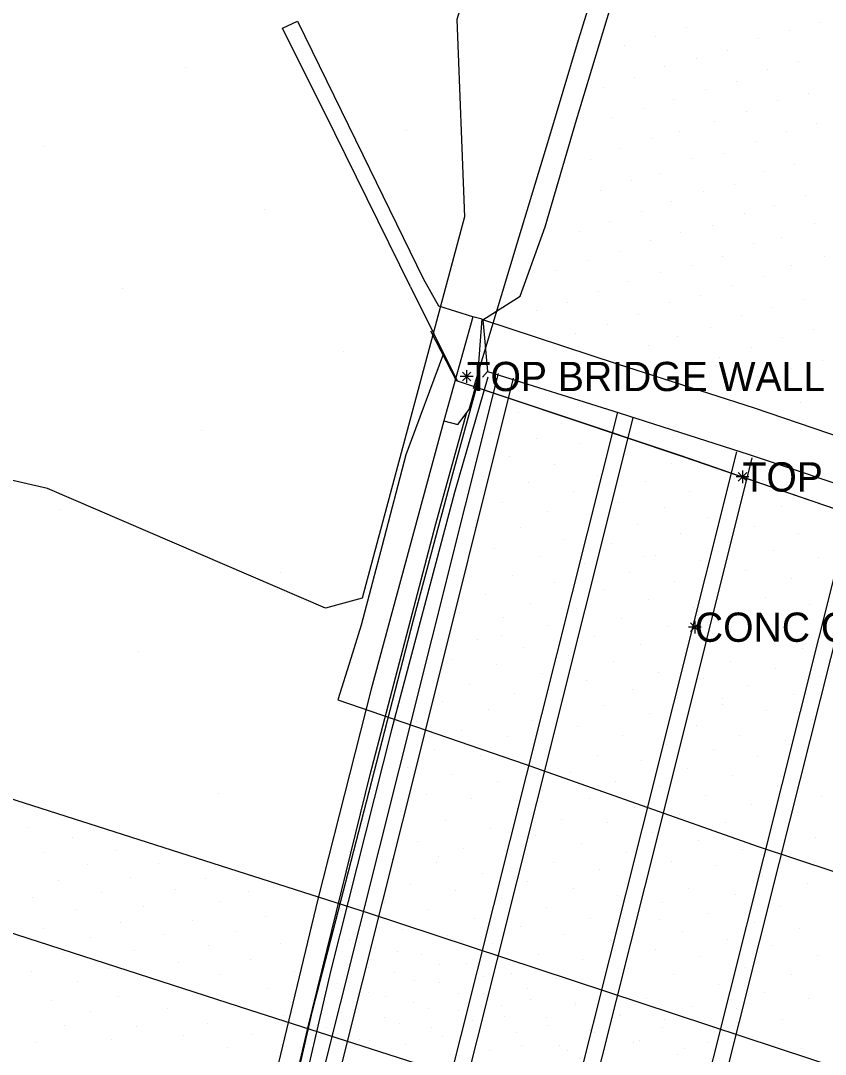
# Model space of a CAD drawing. Extents: x 1733582 to 1734070, y 467256 to 468256.
# Drawn here: x 1733826.4 to 1733875.9, y 467813.1 to 467876.7 of the extents above; entities that cross this region are included whole.
import ezdxf

# ---------------------------------------------------------------- set-up
doc = ezdxf.new("R2010")
doc.units = 0
for name, color, linetype in [('Default', 7, 'Continuous'), ('S_Bridge_Abutment_Bottom', 7, 'Continuous'), ('S_Bridge_Curb', 7, 'Continuous'), ('S_Bridge_Deck', 7, 'Continuous'), ('S_Bridge_ExpansionJoint', 7, 'Continuous'), ('S_Bridge_Parapet', 7, 'Continuous'), ('S_Bridge_Rail', 7, 'Continuous'), ('S_Bridge_Wingwall', 7, 'Continuous'), ('S_Ground_LevelString', 7, 'Continuous'), ('S_Ground_SpotElevation', 7, 'Continuous'), ('S_Guardrail_Beam', 7, 'Continuous'), ('S_Misc_MiscFeature', 7, 'Continuous'), ('S_Misc_MiscItems', 7, 'Continuous'), ('S_Roadway_Edge_Pavement', 7, 'Continuous'), ('S_Roadway_Painted_Lines', 7, 'Continuous'), ('S_Text', 7, 'Continuous'), ('S_Trees_Bush_Line', 7, 'Continuous')]:
    doc.layers.add(name, color=color, linetype=linetype)

# ---------------------------------------------------------------- blocks, each defined once
blk = doc.blocks.new('POINT_DISPLAY')
at = {"layer": 'Default'}
blk.add_line((0, 0), (0, 0), dxfattribs=at)

msp = doc.modelspace()

# ---------------------------------------------------------------- linework, layer by layer
at = {"layer": 'S_Bridge_Abutment_Bottom'}
for points in [[(1733850.373, 467860.35), (1733853.263, 467854.563), (1733867.149, 467849.901), (1733879.209, 467845.764), (1733887.663, 467842.899), (1733893.569, 467845.839)], [(1733852.42, 467856.251), (1733850.086, 467849.997), (1733848.643, 467844.425), (1733847.351, 467839.52), (1733846.701, 467837.477), (1733845.911, 467834.929), (1733857.447, 467830.97), (1733871.792, 467825.895), (1733883.518, 467822.024), (1733885.278, 467828.551), (1733887.725, 467837.781), (1733888.645, 467841.491), (1733889.276, 467843.701)]]:
    msp.add_lwpolyline(points, dxfattribs=at)
at = {"layer": 'S_Bridge_Curb'}
msp.add_lwpolyline([(1733818.159, 467663.732), (1733819.385, 467674.582), (1733820.64, 467684.116), (1733822.243, 467697.564), (1733823.972, 467709.579), (1733825.87, 467722.342), (1733827.859, 467734.138), (1733830.216, 467748.192), (1733832.11, 467758.256), (1733834.51, 467770.45), (1733837.898, 467787.063), (1733840.865, 467800.549), (1733844.359, 467815.787), (1733847.831, 467829.289), (1733850.56, 467839.861), (1733853.05, 467849.061), (1733854.563, 467854.584)], dxfattribs=at)
at = {"layer": 'S_Bridge_Deck'}
msp.add_line((1733854.822, 467854.785), (1733855.12, 467855.138), dxfattribs=at)
msp.add_lwpolyline([(1733855.138, 467854.785), (1733853.086, 467847.693), (1733849.22, 467833.073), (1733845.482, 467818.291), (1733842.048, 467803.532), (1733838.704, 467788.663), (1733835.558, 467773.547), (1733832.728, 467759.072), (1733829.896, 467743.681), (1733827.379, 467728.743), (1733824.957, 467713.563), (1733822.869, 467698.529), (1733821.029, 467683.583), (1733819.201, 467668.729), (1733818.621, 467663.409)], dxfattribs=at)
at = {"layer": 'S_Bridge_ExpansionJoint'}
for points in [[(1733888.515, 467847.187), (1733886.678, 467847.805), (1733878.85, 467850.396), (1733871.551, 467852.887), (1733863.133, 467855.581), (1733854.845, 467858.314)], [(1733888.515, 467847.187), (1733886.678, 467847.805), (1733878.85, 467850.396), (1733871.551, 467852.887), (1733863.133, 467855.581), (1733854.845, 467858.314), (1733855.12, 467855.138), (1733863.226, 467852.582), (1733871.238, 467850.017), (1733878.782, 467847.499), (1733886.695, 467844.816), (1733888.515, 467847.187)]]:
    msp.add_lwpolyline(points, dxfattribs=at)
at = {"layer": 'S_Bridge_Parapet'}
msp.add_lwpolyline([(1733853.286, 467851.862), (1733854, 467852.799), (1733854.498, 467854.603), (1733854.801, 467858.354), (1733854.221, 467858.497), (1733852.432, 467852.088), (1733853.286, 467851.862)], dxfattribs=at)
at = {"layer": 'S_Bridge_Rail'}
msp.add_lwpolyline([(1733818.359, 467665.855), (1733819.171, 467673.048), (1733821.039, 467688.917), (1733823.113, 467704.785), (1733825.46, 467720.602), (1733828.058, 467736.434), (1733830.845, 467752.168), (1733833.805, 467767.85), (1733837.016, 467783.594), (1733840.405, 467799.172), (1733844.065, 467814.724), (1733847.908, 467830.326), (1733851.933, 467845.769), (1733853.853, 467852.641)], dxfattribs=at)
at = {"layer": 'S_Bridge_Wingwall'}
for points in [[(1733850.373, 467860.35), (1733845.718, 467869.802), (1733842.498, 467876.263), (1733843.416, 467876.693)], [(1733850.373, 467860.35), (1733845.718, 467869.802), (1733842.498, 467876.263), (1733843.416, 467876.693)], [(1733843.416, 467876.693), (1733847.44, 467868.46), (1733851.164, 467860.849)], [(1733851.164, 467860.849), (1733852.099, 467859.174), (1733854.191, 467858.512)]]:
    msp.add_lwpolyline(points, dxfattribs=at)
at = {"layer": 'S_Ground_LevelString'}
msp.add_lwpolyline([(1733852.42, 467856.251), (1733850.086, 467849.997), (1733848.643, 467844.425), (1733847.351, 467839.52), (1733846.701, 467837.477), (1733845.911, 467834.929), (1733857.447, 467830.97), (1733871.792, 467825.895), (1733883.518, 467822.024), (1733885.278, 467828.551), (1733887.725, 467837.781), (1733888.645, 467841.491), (1733889.276, 467843.701)], dxfattribs=at)
at = {"layer": 'S_Guardrail_Beam'}
msp.add_lwpolyline([(1733854.27, 467854.097), (1733857.079, 467863.421), (1733858.901, 467869.438), (1733860.667, 467875.345), (1733863.417, 467884.252), (1733867.149, 467896.174), (1733870.976, 467908.127), (1733874.829, 467920.063), (1733878.684, 467931.805), (1733882.613, 467943.748), (1733886.481, 467955.744), (1733888.25, 467961.715), (1733889.83, 467967.648), (1733891.464, 467973.858), (1733891.813, 467975.524), (1733892.138, 467977.915), (1733892.283, 467980.088), (1733892.308, 467981.408), (1733892.214, 467983.277), (1733891.951, 467985.659), (1733891.686, 467987.183)], dxfattribs=at)
at = {"layer": 'S_Misc_MiscFeature'}
for points in [[(1733851.612, 467857.638), (1733853.196, 467854.581), (1733859.544, 467852.463), (1733859.587, 467852.455), (1733866.898, 467850.008), (1733866.968, 467849.988), (1733874.19, 467847.475), (1733874.253, 467847.466), (1733881.575, 467844.967), (1733881.654, 467844.95), (1733887.649, 467842.907), (1733890.85, 467844.587)], [(1733851.612, 467857.638), (1733853.196, 467854.581), (1733859.544, 467852.463), (1733859.587, 467852.455), (1733866.898, 467850.008), (1733866.968, 467849.988), (1733874.19, 467847.475), (1733874.253, 467847.466), (1733881.575, 467844.967), (1733881.654, 467844.95), (1733887.649, 467842.907), (1733890.85, 467844.587)], [(1733819.146, 467662.128), (1733822.411, 467687.138), (1733825.625, 467712.064), (1733828.308, 467732.621), (1733831.184, 467747.947), (1733833.505, 467760.094), (1733835.806, 467771.99), (1733838.257, 467784.633), (1733839.477, 467789.916), (1733843.642, 467806.605), (1733849.69, 467830.62), (1733855.796, 467855.018)], [(1733820.122, 467661.91), (1733823.472, 467687.541), (1733826.672, 467712.367), (1733829.355, 467732.542), (1733832.44, 467748.988), (1733834.659, 467760.701), (1733836.916, 467772.404), (1733839.778, 467786.991), (1733844.946, 467807.685), (1733851.172, 467832.455), (1733856.733, 467854.727)], [(1733826.53, 467660.119), (1733830.278, 467688.775), (1733833.202, 467711.396), (1733835.635, 467730.109), (1733838.854, 467747.125), (1733841.053, 467758.65), (1733843.35, 467770.62), (1733845.821, 467783.336), (1733847.212, 467789.204), (1733851.47, 467806.186), (1733857.516, 467830.268), (1733863.15, 467852.64)], [(1733852.432, 467852.088), (1733847.956, 467835.582), (1733844.668, 467822.664), (1733840.962, 467807.205), (1733837.376, 467791.545), (1733834.11, 467775.918), (1733831.093, 467760.248), (1733828.17, 467744.438), (1733825.424, 467728.718), (1733822.802, 467711.353), (1733820.741, 467696.705), (1733817.897, 467673.275), (1733817.169, 467667.027)], [(1733864.079, 467852.275), (1733858.131, 467828.607), (1733852.049, 467804.339), (1733847.192, 467785.066), (1733844.207, 467769.696), (1733841.988, 467758.102), (1733839.394, 467744.549), (1733836.696, 467730.312), (1733833.835, 467708.583), (1733831.31, 467688.992), (1733827.509, 467659.844)], [(1733833.862, 467657.682), (1733837.178, 467683.156), (1733840.254, 467706.86), (1733843.003, 467727.895), (1733846.149, 467744.535), (1733848.346, 467756.071), (1733850.647, 467768.07), (1733853.573, 467783.047), (1733858.608, 467802.95), (1733864.671, 467827.038), (1733870.472, 467850.181)], [(1733871.393, 467849.822), (1733865.695, 467826.963), (1733859.504, 467802.42), (1733854.508, 467782.647), (1733851.621, 467767.768), (1733849.286, 467755.703), (1733847.085, 467744.185), (1733843.99, 467727.733), (1733841.143, 467705.862), (1733838.187, 467683.149), (1733834.828, 467657.424)], [(1733841.162, 467655.238), (1733844.601, 467681.503), (1733847.732, 467705.748), (1733850.338, 467725.565), (1733853.469, 467742.079), (1733855.705, 467753.836), (1733857.987, 467765.604), (1733860.885, 467780.409), (1733865.914, 467800.487), (1733872.136, 467825.216), (1733877.778, 467847.684)], [(1733878.753, 467847.484), (1733873.086, 467824.941), (1733866.9, 467800.334), (1733861.829, 467780.055), (1733858.912, 467765.093), (1733856.608, 467753.207), (1733854.359, 467741.368), (1733851.322, 467725.26), (1733848.676, 467705.17), (1733845.544, 467680.934), (1733842.168, 467654.979)]]:
    msp.add_lwpolyline(points, dxfattribs=at)
at = {"layer": 'S_Misc_MiscItems'}
for p, q in [((1733854.1, 467854.566), (1733853.576, 467855.09)), ((1733854.1, 467855.09), (1733853.576, 467854.566)), ((1733853.838, 467855.221), (1733853.838, 467854.435)), ((1733854.231, 467854.828), (1733853.445, 467854.828)), ((1733871.216, 467848.646), (1733870.43, 467848.646)), ((1733871.085, 467848.384), (1733870.561, 467848.908)), ((1733871.085, 467848.908), (1733870.561, 467848.384)), ((1733870.823, 467849.039), (1733870.823, 467848.253)), ((1733868.153, 467839.136), (1733867.629, 467839.66)), ((1733868.153, 467839.66), (1733867.629, 467839.136)), ((1733867.891, 467839.791), (1733867.891, 467839.005)), ((1733868.284, 467839.398), (1733867.498, 467839.398))]:
    msp.add_line(p, q, dxfattribs=at)
at = {"layer": 'S_Roadway_Edge_Pavement'}
for points in [[(1733854.845, 467858.314), (1733857.128, 467859.768), (1733858.674, 467864.047), (1733860.603, 467870.622), (1733863.432, 467879.992), (1733866.984, 467890.771), (1733869.633, 467899.006), (1733872.574, 467908.264), (1733875.889, 467918.696)], [(1734069.119, 467746.597), (1734001.211, 467770.208), (1733956.123, 467785.373), (1733927.716, 467795.111), (1733887.65, 467808.651), (1733847.805, 467821.807), (1733798.866, 467837.428), (1733790.266, 467840.778), (1733759.652, 467856.03), (1733727.307, 467874.285), (1733717.915, 467873.615), (1733694.164, 467877.415), (1733655.646, 467887.316), (1733629.579, 467895.037)]]:
    msp.add_lwpolyline(points, dxfattribs=at)
at = {"layer": 'S_Roadway_Painted_Lines'}
msp.add_lwpolyline([(1733625.204, 467882.39), (1733667.524, 467869.887), (1733714.43, 467855.622), (1733753.6, 467843.716), (1733799.459, 467829.092), (1733840.473, 467815.848), (1733894.111, 467798.664), (1733961.084, 467775.678), (1734014.318, 467757.225), (1734066.93, 467738.782)], dxfattribs=at)
at = {"layer": 'S_Trees_Bush_Line'}
msp.add_lwpolyline([(1733864.99, 467914.699), (1733853.241, 467876.8), (1733853.702, 467864.648), (1733847.41, 467841.194), (1733845.154, 467840.576), (1733828.035, 467847.94), (1733810.332, 467852), (1733780.088, 467867.503), (1733752.541, 467872.718), (1733724.887, 467879.082), (1733700.627, 467880.361), (1733664.82, 467890.7), (1733633.561, 467903.194)], dxfattribs=at)

# ---------------------------------------------------------------- block references
at = {"layer": 'S_Ground_SpotElevation'}
for p in [(1733875.587, 467876.608), (1733867.371, 467876.303), (1733873.706, 467876.117), (1733865.476, 467875.748), (1733871.809, 467875.616), (1733863.542, 467875.214), (1733869.893, 467874.902), (1733867.978, 467874.383), (1733874.263, 467874.198), (1733836.545, 467873.821), (1733866.037, 467873.883), (1733872.388, 467873.738), (1733864.152, 467873.242), (1733870.464, 467873.007), (1733862.247, 467872.606), (1733868.57, 467872.503), (1733874.856, 467872.249), (1733866.586, 467871.843), (1733872.962, 467871.841), (1733864.714, 467871.335), (1733871.044, 467871.128), (1733862.837, 467870.759), (1733869.127, 467870.492), (1733875.407, 467870.41), (1733850.147, 467869.949), (1733866.954, 467869.902), (1733873.555, 467869.89), (1733827.808, 467868.956), (1733865.3, 467869.468), (1733871.634, 467869.264), (1733863.319, 467868.831), (1733869.723, 467868.562), (1733861.439, 467868.168), (1733867.745, 467868.213), (1733874.05, 467867.872), (1733865.802, 467867.307), (1733872.205, 467867.42), (1733863.984, 467866.911), (1733870.305, 467866.627), (1733862.06, 467866.27), (1733868.424, 467866.195), (1733874.698, 467865.993), (1733841.41, 467865.084), (1733866.433, 467865.61), (1733872.774, 467865.339), (1733864.591, 467865.008), (1733870.915, 467864.877), (1733862.603, 467864.347), (1733868.954, 467864.1), (1733875.251, 467864.22), (1733860.783, 467863.779), (1733865.127, 467863.18), (1733867.001, 467863.698), (1733873.208, 467863.375), (1733871.491, 467862.999), (1733861.262, 467861.975), (1733863.237, 467862.495), (1733869.565, 467862.214), (1733875.879, 467862.217), (1733859.308, 467861.374), (1733867.675, 467861.684), (1733873.836, 467861.627), (1733863.772, 467860.694), (1733865.76, 467861.206), (1733872.083, 467860.953), (1733832.674, 467860.219), (1733861.95, 467860.027), (1733870.127, 467860.449), (1733860.043, 467859.394), (1733866.332, 467859.35), (1733868.229, 467859.829), (1733874.569, 467859.589), (1733858.114, 467858.886), (1733872.685, 467859.085), (1733864.4, 467858.619), (1733870.757, 467858.562), (1733860.564, 467857.484), (1733862.502, 467858.056), (1733868.856, 467857.861), (1733875.184, 467857.742), (1733866.821, 467857.287), (1733873.254, 467857.212), (1733846.275, 467856.347), (1733865.006, 467856.711), (1733871.369, 467856.622), (1733869.424, 467855.975), (1733875.741, 467855.826), (1733867.532, 467855.475), (1733873.848, 467855.304), (1733871.749, 467854.826), (1733874.373, 467853.252), (1733857.019, 467852.591), (1733859.659, 467851.91), (1733837.539, 467851.482), (1733855.323, 467851.346), (1733862.458, 467851.65), (1733858.13, 467851.01), (1733860.804, 467850.682), (1733865.083, 467850.901), (1733856.503, 467849.904), (1733863.615, 467850.024), (1733859.233, 467849.437), (1733866.431, 467849.443), (1733854.866, 467848.691), (1733861.923, 467848.733), (1733869.309, 467849.024), (1733857.656, 467848.283), (1733864.838, 467848.342), (1733872.032, 467848.448), (1733860.446, 467847.746), (1733867.576, 467847.739), (1733870.439, 467847.394), (1733874.643, 467847.762), (1733828.802, 467846.617), (1733856.02, 467847.088), (1733863.184, 467847.054), (1733866.002, 467846.756), (1733873.207, 467846.847), (1733858.793, 467846.49), (1733861.517, 467846.195), (1733868.731, 467846.118), (1733854.364, 467845.94), (1733857.129, 467845.536), (1733864.338, 467845.698), (1733871.543, 467845.581), (1733859.821, 467844.781), (1733867.023, 467845.191), (1733874.254, 467845.149), (1733855.538, 467844.247), (1733862.731, 467844.518), (1733869.942, 467844.611), (1733872.731, 467844.11), (1733858.297, 467843.736), (1733864.742, 467843.739), (1733865.489, 467843.824), (1733868.262, 467843.501), (1733875.517, 467843.66), (1733853.835, 467843.175), (1733861.073, 467843.3), (1733871.017, 467842.858), (1733842.403, 467842.745), (1733856.665, 467842.568), (1733863.84, 467842.744), (1733866.606, 467842.2), (1733873.809, 467842.398), (1733859.249, 467842.126), (1733862.234, 467841.721), (1733869.395, 467841.744), (1733854.976, 467841.383), (1733865.029, 467841.085), (1733872.225, 467841.225), (1733853.393, 467840.319), (1733857.742, 467840.829), (1733860.601, 467840.564), (1733867.815, 467840.58), (1733874.964, 467840.807), (1733856.114, 467840.017), (1733863.388, 467839.951), (1733870.597, 467840.113), (1733873.267, 467839.752), (1733858.893, 467839.492), (1733866.177, 467839.466), (1733868.953, 467839.037), (1733854.509, 467838.612), (1733856.005, 467838.874), (1733861.719, 467838.848), (1733871.743, 467838.557), (1733833.667, 467837.88), (1733857.309, 467838.16), (1733864.545, 467838.337), (1733867.275, 467837.783), (1733874.535, 467838.059), (1733852.887, 467837.436), (1733855.652, 467837.113), (1733860.083, 467837.684), (1733862.868, 467837.264), (1733870.094, 467837.275), (1733851.217, 467836.543), (1733858.482, 467836.541), (1733865.644, 467836.596), (1733872.832, 467836.842), (1733854.032, 467835.879), (1733861.238, 467836.108), (1733868.432, 467836.218), (1733875.61, 467836.381), (1733856.796, 467835.344), (1733864.024, 467835.533), (1733871.172, 467835.78), (1733873.979, 467835.276), (1733852.374, 467834.811), (1733859.619, 467834.969), (1733862.354, 467834.56), (1733866.8, 467835.092), (1733869.59, 467834.648), (1733869.607, 467835.002), (1733855.169, 467834.332), (1733865.104, 467834.069), (1733872.29, 467834.249), (1733850.722, 467833.611), (1733857.886, 467833.632), (1733860.688, 467833.276), (1733867.963, 467833.334), (1733875.14, 467833.722), (1733853.547, 467833.062), (1733856.332, 467832.674), (1733863.464, 467832.72), (1733870.66, 467832.741), (1733859.078, 467832.021), (1733866.172, 467832.169), (1733873.498, 467832.409), (1733851.846, 467831.865), (1733854.703, 467831.511), (1733861.875, 467831.496), (1733869.039, 467831.852), (1733871.757, 467831.431), (1733850.204, 467830.763), (1733857.482, 467830.96), (1733864.607, 467831.189), (1733874.657, 467830.865), (1733852.982, 467830.335), (1733860.225, 467830.468), (1733867.456, 467830.699), (1733870.217, 467830.263), (1733855.711, 467829.915), (1733862.986, 467829.908), (1733865.797, 467829.592), (1733872.972, 467829.572), (1733838.532, 467829.144), (1733851.364, 467829.072), (1733854.147, 467828.846), (1733858.518, 467829.343), (1733861.4, 467828.875), (1733868.522, 467829.015), (1733875.706, 467829.001), (1733856.953, 467828.211), (1733864.184, 467828.294), (1733871.388, 467828.458), (1733849.757, 467828.03), (1733859.687, 467827.537), (1733866.942, 467827.849), (1733874.186, 467827.963), (1733826.774, 467827.096), (1733852.556, 467827.528), (1733855.324, 467826.984), (1733862.481, 467827.376), (1733869.746, 467827.381), (1733829.602, 467826.466), (1733858.076, 467826.583), (1733865.258, 467826.779), (1733868.115, 467826.27), (1733872.481, 467826.764), (1733875.333, 467826.438), (1733832.222, 467825.66), (1733850.84, 467826.232), (1733853.651, 467825.802), (1733860.914, 467826.088), (1733870.81, 467825.707), (1733827.814, 467825.522), (1733849.251, 467825.132), (1733852.134, 467825.272), (1733856.491, 467825.417), (1733863.691, 467825.555), (1733873.673, 467825.182), (1733830.485, 467824.765), (1733834.879, 467824.875), (1733852.009, 467824.916), (1733859.212, 467824.94), (1733862.045, 467824.502), (1733866.462, 467824.982), (1733869.215, 467824.712), (1733828.682, 467823.82), (1733833.162, 467824.004), (1733837.741, 467823.921), (1733854.836, 467824.218), (1733857.584, 467823.732), (1733864.761, 467823.966), (1733872.06, 467824.059), (1733835.891, 467823.258), (1733840.392, 467823.111), (1733850.359, 467823.545), (1733853.176, 467823.201), (1733860.403, 467823.341), (1733867.51, 467823.345), (1733874.824, 467823.617), (1733827.106, 467822.76), (1733831.345, 467823.047), (1733838.618, 467822.513), (1733848.764, 467822.458), (1733855.964, 467822.692), (1733863.142, 467822.856), (1733865.894, 467822.464), (1733870.419, 467822.951), (1733829.802, 467822.022), (1733833.971, 467822.218), (1733851.446, 467822.023), (1733858.774, 467822.152), (1733873.1, 467822.238), (1733832.501, 467821.254), (1733836.944, 467821.372), (1733841.485, 467821.623), (1733854.341, 467821.443), (1733861.458, 467821.488), (1733865.735, 467821.4), (1733868.708, 467821.755), (1733871.538, 467821.254), (1733827.794, 467820.879), (1733839.684, 467820.689), (1733844.204, 467820.916), (1733849.918, 467820.794), (1733857.129, 467820.963), (1733864.281, 467821.081), (1733867.117, 467820.642), (1733874.313, 467820.826), (1733830.68, 467820.292), (1733835.204, 467820.483), (1733842.358, 467819.947), (1733846.651, 467820.158), (1733852.681, 467820.44), (1733855.439, 467819.952), (1733859.825, 467820.493), (1733862.665, 467820.096), (1733869.9, 467820.171), (1733828.952, 467819.368), (1733833.388, 467819.498), (1733837.93, 467819.779), (1733848.249, 467819.706), (1733849.596, 467819.42), (1733865.453, 467819.533), (1733872.597, 467819.832), (1733836.085, 467818.782), (1733840.516, 467818.97), (1733845.077, 467819.204), (1733846.61, 467818.645), (1733851.051, 467819.23), (1733853.804, 467818.726), (1733858.236, 467819.249), (1733860.979, 467818.942), (1733868.245, 467819.122), (1733875.419, 467819.167), (1733827.04, 467818.208), (1733831.772, 467818.376), (1733838.687, 467818.001), (1733843.216, 467818.223), (1733847.782, 467818.477), (1733849.409, 467818.173), (1733852.147, 467818.615), (1733856.588, 467818.055), (1733863.779, 467818.414), (1733866.567, 467818.036), (1733871.025, 467818.484), (1733873.82, 467818.007), (1733829.869, 467817.591), (1733834.351, 467817.771), (1733845.887, 467817.454), (1733850.641, 467817.624), (1733852.188, 467817.516), (1733854.906, 467817.922), (1733859.347, 467817.779), (1733869.35, 467817.412), (1733836.962, 467816.752), (1733841.643, 467817.174), (1733847.801, 467816.9), (1733853.34, 467816.883), (1733854.895, 467816.885), (1733857.597, 467817.146), (1733862.124, 467817.032), (1733872.2, 467816.936), (1733828.285, 467816.443), (1733832.425, 467816.697), (1733839.836, 467816.29), (1733844.367, 467816.45), (1733848.845, 467816.678), (1733850.539, 467816.298), (1733856.01, 467816.102), (1733857.782, 467816.485), (1733860.504, 467816.288), (1733860.536, 467816.189), (1733864.935, 467816.555), (1733874.88, 467816.562), (1733830.692, 467815.736), (1733835.396, 467815.927), (1733842.572, 467815.474), (1733846.14, 467815.713), (1733847.016, 467815.702), (1733851.499, 467815.919), (1733853.332, 467815.791), (1733856.154, 467815.461), (1733863.251, 467815.566), (1733863.304, 467815.48), (1733867.725, 467816.074), (1733870.463, 467815.932), (1733829.099, 467814.909), (1733833.544, 467814.85), (1733837.894, 467815.024), (1733848.785, 467815.349), (1733849.702, 467814.979), (1733854.215, 467815.176), (1733858.736, 467815.383), (1733858.867, 467814.865), (1733865.994, 467815.276), (1733873.301, 467815.236), (1733836.388, 467814.277), (1733840.675, 467814.362), (1733845.238, 467814.761), (1733851.705, 467814.749), (1733852.373, 467814.203), (1733854.504, 467814.251), (1733856.906, 467814.432), (1733861.419, 467814.616), (1733861.711, 467814.461), (1733865.883, 467814.749), (1733868.829, 467814.596), (1733827.271, 467813.865), (1733831.97, 467814.03), (1733839.109, 467813.546), (1733843.58, 467813.536), (1733847.237, 467814.053), (1733847.836, 467813.957), (1733850.082, 467813.697), (1733857.219, 467813.652), (1733859.561, 467813.642), (1733864.131, 467813.864), (1733864.472, 467813.936), (1733868.688, 467813.85), (1733871.667, 467814.09), (1733852.818, 467813.125), (1733855.273, 467813.331), (1733860.048, 467813.351), (1733866.832, 467813.113), (1733867.254, 467813.492), (1733874.477, 467813.486)]:
    msp.add_blockref('POINT_DISPLAY', p, dxfattribs=at)

# ---------------------------------------------------------------- texts
at = {"layer": 'S_Text'}
for s, p in [('TOP BRIDGE WALL', (1733853.838, 467853.928)), ('TOP OF ABUTMENT WALL', (1733870.823, 467847.746)), ('CONC CLOPE', (1733867.891, 467838.498))]:
    msp.add_text(s, height=1.8, dxfattribs=at).set_placement(p)

doc.saveas('drawing.dxf')
